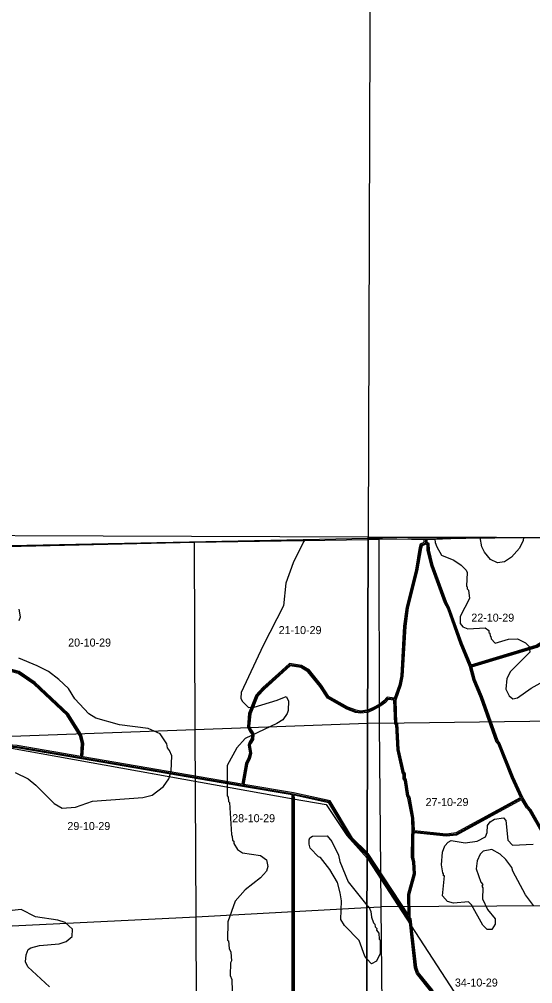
# Model space of a CAD drawing. Extents: x 457167 to 656239, y 1787309 to 1969297.
# Drawn here: x 527283 to 541715, y 1911287 to 1938392 of the extents above; entities that cross this region are included whole.
import ezdxf

# ---------------------------------------------------------------- set-up
doc = ezdxf.new("R2010")
doc.units = 0
for name, color, linetype in [('Level 1', 7, 'Continuous'), ('Level 10', 7, 'Continuous'), ('Level 2', 7, 'Continuous'), ('Level 22', 7, 'Continuous'), ('Level 23', 7, 'Continuous'), ('Level 31', 7, 'Continuous'), ('Level 32', 7, 'Continuous'), ('Level 34', 7, 'Continuous'), ('Level 55', 7, 'Continuous'), ('Level 63', 7, 'Continuous'), ('Level 7', 7, 'Continuous')]:
    doc.layers.add(name, color=color, linetype=linetype)

msp = doc.modelspace()

# ---------------------------------------------------------------- linework, layer by layer
at = {"layer": 'Level 1'}
for p, q in [((532207.788, 1923696.97), (537088.395, 1923773.153)), ((537088.395, 1923773.153), (537386.225, 1923777.802)), ((537386.225, 1923777.802), (541464.725, 1923829.241)), ((537386.225, 1923777.802), (537399.722, 1918609.551)), ((540899.182, 1923825.716), (541279.888, 1923829.737)), ((541279.889, 1923829.737), (541279.89, 1923829.737)), ((541279.89, 1923829.737), (541279.891, 1923829.737)), ((541279.891, 1923829.737), (541279.892, 1923829.737)), ((541279.892, 1923829.737), (541279.894, 1923829.737)), ((541279.894, 1923829.737), (541279.896, 1923829.737)), ((541279.896, 1923829.737), (541279.9, 1923829.737)), ((541279.9, 1923829.737), (541279.904, 1923829.737)), ((541279.904, 1923829.737), (541279.909, 1923829.737)), ((541279.909, 1923829.737), (542660.739, 1923844.323)), ((541464.726, 1923829.241), (541464.727, 1923829.241)), ((541464.726, 1923829.241), (541464.726, 1923829.241)), ((541464.727, 1923829.241), (541464.728, 1923829.241)), ((541464.728, 1923829.241), (541464.73, 1923829.241)), ((541464.73, 1923829.241), (541464.731, 1923829.241)), ((541464.731, 1923829.241), (541464.733, 1923829.241)), ((541464.733, 1923829.241), (541464.736, 1923829.241)), ((541464.736, 1923829.241), (541464.739, 1923829.241)), ((541464.739, 1923829.241), (541464.742, 1923829.241)), ((541464.742, 1923829.241), (541464.746, 1923829.241)), ((541464.746, 1923829.241), (541464.751, 1923829.241)), ((541464.751, 1923829.241), (541464.758, 1923829.241)), ((541464.758, 1923829.241), (541464.766, 1923829.241)), ((541464.766, 1923829.241), (541464.775, 1923829.241)), ((541464.775, 1923829.241), (541464.786, 1923829.241)), ((541464.786, 1923829.241), (541464.801, 1923829.241)), ((541464.801, 1923829.241), (541464.817, 1923829.241)), ((541464.817, 1923829.241), (541464.838, 1923829.241)), ((541464.838, 1923829.241), (541464.863, 1923829.241)), ((526935.17, 1923574.614), (532207.788, 1923696.97)), ((532229.194, 1918419.419), (532207.788, 1923696.97)), ((537071.765, 1918597.492), (532229.194, 1918419.419)), ((537399.722, 1918609.551), (537071.765, 1918597.492)), ((537399.722, 1918609.551), (542688.569, 1918676.008)), ((537399.722, 1918609.551), (537449.415, 1913450.626)), ((532229.194, 1918419.419), (527067.84, 1918235.886)), ((532250.887, 1913167.832), (532229.194, 1918419.419)), ((532250.887, 1913167.832), (537055.159, 1913429.178)), ((537055.159, 1913429.178), (537449.415, 1913450.626)), ((542719.505, 1913479.356), (537449.415, 1913450.626)), ((537449.415, 1913450.626), (537491.16, 1908193.626)), ((527082.764, 1912914.463), (532250.887, 1913167.832)), ((532281.084, 1907962.091), (532250.887, 1913167.832))]:
    msp.add_line(p, q, dxfattribs=at)
at = {"layer": 'Level 10'}
for points in [[(526576.251, 1923593.055), (537088.465, 1923809.196), (537088.51, 1923809.195)], [(537088.51, 1923809.195), (538706.499, 1923767.216), (540123.527, 1923831.236), (542887.584, 1923822.271), (543166.577, 1923824.675)]]:
    msp.add_lwpolyline(points, dxfattribs=at)
at = {"layer": 'Level 22'}
msp.add_line((538706.659, 1923677.254), (538706.944, 1923767.074), dxfattribs=at)
at = {"layer": 'Level 23'}
for p, q in [((538666.706, 1923692.391), (538666.947, 1923768.242)), ((538746.7, 1923689.914), (538746.951, 1923769.043))]:
    msp.add_line(p, q, dxfattribs=at)
at = {"layer": 'Level 31'}
for p, q in [((533564.628, 1916861.349), (529035.771, 1917636.671)), ((534984.082, 1916618.481), (533564.628, 1916861.349)), ((534984.26, 1916478.475), (534984.082, 1916618.481)), ((534986.798, 1910649.551), (534984.26, 1916478.475)), ((537059.931, 1914928.41), (537059.975, 1914928.342)), ((537059.975, 1914928.342), (538245.04, 1913122.737)), ((538270.068, 1913097.566), (538245.04, 1913122.737)), ((538287.69, 1912942.232), (538270.068, 1913097.566))]:
    msp.add_line(p, q, dxfattribs=at)
for points in [[(537851.535, 1919279.466), (537995.881, 1919700.836), (538046.517, 1919934.137), (538125.343, 1921334.296), (538193.43, 1921859.551), (538454.444, 1922900.938), (538564.518, 1923542.428), (538589.884, 1923625.623), (538706.659, 1923677.254)], [(539964.516, 1920212.431), (539699.585, 1920846.741), (539351.88, 1921831.144), (539260.604, 1922006.712), (538888.27, 1923033.017), (538780.977, 1923466.828), (538773.271, 1923641.768), (538706.659, 1923677.254)], [(529035.771, 1917636.671), (529066.382, 1918036.581), (528999.837, 1918277.181), (528641.777, 1918856.254), (527708.613, 1919728.246), (527267.972, 1920034.881), (526943.509, 1920121.473), (526847.193, 1920203.631), (526702.303, 1920661.61), (526702.662, 1920764.158), (526738.365, 1920978.223), (526712.279, 1921060.5), (526639.521, 1921154.576), (526598.766, 1921221.995), (526605.164, 1921415.434), (526552.704, 1921497.803), (526447.68, 1921542.173), (525921.774, 1921538.932)], [(539964.516, 1920212.431), (541825.21, 1920774.286), (542175.76, 1920998.301), (542551.24, 1921064.056), (542726.25, 1921038.791), (542825.899, 1920996.666), (543042.318, 1920795.996), (543300.811, 1920845.391)], [(537072.875, 1918943.056), (537072.848, 1918943.045), (536877.975, 1918920.401), (536740.444, 1918941.571), (536506.835, 1919027.785), (535966.66, 1919337.911), (535754.146, 1919655.341), (535416.143, 1920079.004), (535209.034, 1920200.048), (534887.299, 1920251.286), (534585.16, 1919979.906), (534151.372, 1919586.048), (533960.666, 1919381.581), (533760.062, 1918875.316), (533726.775, 1918515.051), (533781.998, 1918397.41), (533846.189, 1918300.466), (533833.955, 1918156.866), (533769.444, 1918060.348), (533742.835, 1917990.252), (533780.223, 1917764.302), (533741.613, 1917620.789), (533671.195, 1917468.653), (533564.628, 1916861.349)], [(541413.502, 1916507.061), (541148.339, 1917083.175), (540767.405, 1918034.574), (540717.376, 1918092.914), (540270.645, 1919336.169), (540071.99, 1919828.809), (539964.516, 1920212.431)], [(537851.535, 1919279.466), (537636.17, 1919307.065), (537551.665, 1919215.333), (537431.875, 1919120.442), (537230.367, 1919010.541), (537072.875, 1918943.056)], [(538359.919, 1915564.994), (538344.27, 1915940.328), (538237.412, 1916515.596), (538204.203, 1916565.886), (538138.556, 1917007.927), (538105.346, 1917057.854), (538105.745, 1917182.947), (538080.693, 1917199.756), (537932.505, 1917866.796), (537892.849, 1918584.037), (537867.798, 1918600.846), (537844.48, 1919259.487), (537851.535, 1919279.466)], [(529035.771, 1917636.671), (527219.39, 1917948.064), (526544.584, 1918000.608), (524894.144, 1918048.616), (524727.453, 1918090.664)], [(537059.931, 1914928.41), (536630.054, 1915361.81), (536000.334, 1916398.066), (534984.082, 1916618.481)], [(538359.919, 1915564.994), (539285.086, 1915470.782), (539568.359, 1915503.345), (541413.502, 1916507.061)], [(543546.401, 1912891.67), (541977.92, 1915580.194), (541646.004, 1916156.511), (541563.023, 1916248.406), (541413.502, 1916507.061)], [(538245.04, 1913122.737), (538230.028, 1913798.078), (538390.159, 1914381.223), (538374.35, 1914706.376), (538341.403, 1914839.939), (538342.995, 1915439.953), (538359.919, 1915564.994)], [(538909.852, 1909277.964), (538938.548, 1910611.731), (538972.581, 1910819.993), (538881.566, 1911086.835), (538474.405, 1911588.142), (538424.664, 1911738.486), (538287.69, 1912942.232)]]:
    msp.add_lwpolyline(points, dxfattribs=at)
at = {"layer": 'Level 32'}
for p, q in [((533559.566, 1916831.778), (529030.71, 1917607.1)), ((533540.244, 1916895.96), (529067.772, 1917661.628)), ((534954.115, 1916593.171), (533559.57, 1916831.777)), ((534989.795, 1916647.94), (533599.385, 1916885.838)), ((534954.26, 1916478.437), (534954.115, 1916593.171)), ((534956.786, 1910679.27), (534954.26, 1916478.461)), ((535014.26, 1916478.512), (535014.13, 1916581.265)), ((535016.789, 1910672.371), (535014.26, 1916478.488)), ((537036.507, 1914909.425), (537059.801, 1914873.933)), ((537059.801, 1914873.933), (538221.626, 1913103.736)), ((537083.357, 1914947.392), (537060.112, 1914970.828)), ((537083.357, 1914947.392), (538212.722, 1913226.652)), ((538241.436, 1913083.812), (538221.625, 1913103.736)), ((538257.881, 1912938.851), (538241.436, 1913083.812)), ((538298.702, 1913111.317), (538274.768, 1913135.388)), ((538317.5, 1912945.614), (538298.702, 1913111.317))]:
    msp.add_line(p, q, dxfattribs=at)
for points in [[(537831.084, 1919312.332), (537966.935, 1919708.906), (538016.697, 1919938.186), (538095.451, 1921337.072), (538163.903, 1921865.146), (538425.067, 1922907.131), (538535.27, 1923549.366), (538565.192, 1923647.509), (538666.706, 1923692.391)], [(537879.917, 1919269.742), (538024.829, 1919692.766), (538076.337, 1919930.087), (538155.235, 1921331.521), (538222.956, 1921853.958), (538483.82, 1922894.745), (538593.765, 1923535.489), (538614.575, 1923603.738), (538705.438, 1923643.911)], [(539936.125, 1920202.566), (539671.579, 1920835.956), (539324.292, 1921819.171), (539233.075, 1921994.625), (538859.527, 1923024.276), (538751.138, 1923462.524), (538744.053, 1923623.341), (538705.439, 1923643.911)], [(539981.765, 1920248.976), (539727.593, 1920857.527), (539379.468, 1921843.118), (539288.133, 1922018.8), (538917.013, 1923041.759), (538810.817, 1923471.132), (538802.489, 1923660.196), (538746.7, 1923689.915)], [(529067.771, 1917661.628), (529096.696, 1918039.521), (529027.609, 1918289.311), (528665.188, 1918875.439), (527727.52, 1919751.638), (527280.79, 1920062.511), (526957.81, 1920148.707), (526873.204, 1920220.877), (526732.32, 1920666.191), (526732.654, 1920761.621), (526769.145, 1920980.408), (526739.267, 1921074.642), (526664.305, 1921171.569), (526629.045, 1921229.898), (526635.455, 1921423.721), (526572.988, 1921521.801), (526453.669, 1921572.211), (525921.589, 1921568.932)], [(529008.374, 1917671.806), (529036.068, 1918033.639), (528972.065, 1918265.051), (528618.367, 1918837.07), (527689.706, 1919704.853), (527255.154, 1920007.251), (526929.209, 1920094.239), (526821.183, 1920186.386), (526672.285, 1920657.029), (526672.67, 1920766.696), (526707.585, 1920976.037), (526685.29, 1921046.357), (526614.738, 1921137.584), (526568.487, 1921214.091), (526574.872, 1921407.147), (526532.42, 1921473.805), (526441.691, 1921512.135), (525921.958, 1921508.932)], [(539981.765, 1920248.977), (541812.559, 1920801.803), (542164.667, 1921026.816), (542550.785, 1921094.434), (542734.366, 1921067.931), (542842.433, 1921022.248), (543051.59, 1920828.311), (543265.744, 1920869.232)], [(540001.337, 1920192.21), (541837.861, 1920746.767), (542186.852, 1920969.786), (542551.695, 1921033.68), (542718.134, 1921009.651), (542809.365, 1920971.085), (543033.045, 1920763.681), (543308.093, 1920816.237)], [(537072.98, 1918975.741), (537065.046, 1918972.341), (536878.535, 1918950.668), (536747.995, 1918970.763), (536519.586, 1919055.057), (535987.685, 1919360.433), (535778.379, 1919673.071), (535436.108, 1920102.084), (535219.31, 1920228.79), (534877.892, 1920283.162), (534565.053, 1920002.171), (534130.283, 1919607.422), (533934.863, 1919397.9), (533730.585, 1918882.365), (533696.15, 1918509.688), (533755.773, 1918382.676), (533815.41, 1918292.61), (533804.719, 1918167.112), (533742.606, 1918074.184), (533711.916, 1917993.336), (533749.563, 1917765.819), (533713.309, 1917631.061), (533642.323, 1917477.699), (533540.243, 1916895.96)], [(537072.778, 1918912.835), (536877.415, 1918890.133), (536732.892, 1918912.38), (536494.083, 1919000.512), (535945.636, 1919315.388), (535729.913, 1919637.61), (535396.178, 1920055.924), (535198.756, 1920171.306), (534896.705, 1920219.41), (534605.268, 1919957.641), (534172.461, 1919564.675), (533986.47, 1919365.261), (533789.54, 1918868.268), (533757.398, 1918520.414), (533808.224, 1918412.144), (533876.967, 1918308.324), (533863.192, 1918146.619), (533796.281, 1918046.512), (533773.754, 1917987.168), (533810.882, 1917762.786), (533769.916, 1917610.517), (533700.066, 1917459.607), (533599.386, 1916885.838)], [(541374.519, 1916520.005), (541120.77, 1917071.32), (540741.4, 1918018.813), (540691.01, 1918077.575), (540242.606, 1919325.482), (540043.548, 1919819.123), (539936.125, 1920202.566)], [(541440.174, 1916520.868), (541175.908, 1917095.029), (540793.41, 1918050.335), (540743.744, 1918108.253), (540298.684, 1919346.856), (540100.432, 1919838.495), (540001.337, 1920192.211)], [(537814.658, 1919253.946), (537647.732, 1919275.337), (537572.136, 1919193.277), (537448.493, 1919095.333), (537243.487, 1918983.523), (537080.649, 1918913.749), (537072.778, 1918912.835)], [(537831.083, 1919312.332), (537624.607, 1919338.793), (537531.193, 1919237.39), (537415.258, 1919145.551), (537217.247, 1919037.557), (537072.98, 1918975.741)], [(538329.835, 1915566.391), (538314.385, 1915936.946), (538209.026, 1916504.139), (538175.504, 1916554.902), (538109.865, 1916996.891), (538075.316, 1917048.831), (538075.693, 1917166.982), (538054.009, 1917181.531), (537902.687, 1917862.687), (537863.72, 1918567.454), (537838.358, 1918584.471), (537814.658, 1919253.946)], [(538388.811, 1915592.207), (538374.155, 1915943.71), (538265.797, 1916527.053), (538232.901, 1916576.87), (538167.246, 1917018.963), (538135.376, 1917066.877), (538135.797, 1917198.911), (538107.376, 1917217.981), (537962.325, 1917870.905), (537921.979, 1918600.621), (537897.237, 1918617.221), (537874.664, 1919254.863), (537879.917, 1919269.742)], [(529030.703, 1917607.101), (527215.683, 1917918.261), (526542.982, 1917970.641), (524889.989, 1918018.723), (524712.034, 1918063.612)], [(529008.374, 1917671.806), (527223.097, 1917977.867), (526546.185, 1918030.575), (524898.298, 1918078.508), (524742.874, 1918117.714)], [(537060.112, 1914970.828), (536653.85, 1915380.42), (536019.282, 1916424.655), (534989.795, 1916647.939)], [(537036.507, 1914909.425), (536606.257, 1915343.2), (535981.385, 1916371.478), (535014.13, 1916581.266)], [(538385.756, 1915532.206), (539285.281, 1915440.606), (539577.575, 1915474.206), (541402.16, 1916466.736)], [(538388.811, 1915592.206), (539284.89, 1915500.958), (539559.142, 1915532.483), (541374.519, 1916520.006)], [(543520.965, 1912875.735), (541951.965, 1915565.148), (541621.599, 1916138.773), (541538.635, 1916230.651), (541402.16, 1916466.736)], [(543554.613, 1912937.13), (542003.876, 1915595.24), (541670.408, 1916174.248), (541587.411, 1916266.162), (541440.174, 1916520.868)], [(538212.722, 1913226.652), (538199.937, 1913801.795), (538359.961, 1914384.55), (538344.525, 1914702.014), (538311.393, 1914836.332), (538312.999, 1915442.013), (538329.835, 1915566.391)], [(538274.768, 1913135.388), (538260.119, 1913794.362), (538420.357, 1914377.897), (538404.173, 1914710.736), (538371.414, 1914843.545), (538372.99, 1915437.892), (538385.755, 1915532.206)], [(538880.801, 1909322.385), (538908.6, 1910614.486), (538941.761, 1910817.417), (538854.901, 1911072.079), (538447.651, 1911573.497), (538395.206, 1911732.011), (538257.882, 1912938.841)], [(538940.499, 1909307.654), (538968.495, 1910608.975), (539003.4, 1910822.568), (538908.232, 1911101.591), (538501.16, 1911602.786), (538454.121, 1911744.963), (538317.498, 1912945.625)]]:
    msp.add_lwpolyline(points, dxfattribs=at)
at = {"layer": 'Level 55'}
for p, q in [((537059.6, 1914811.626), (537106.107, 1914759.527)), ((538287.69, 1912942.232), (537106.107, 1914759.527)), ((540760.35, 1909140.507), (538287.69, 1912942.232))]:
    msp.add_line(p, q, dxfattribs=at)
for points in [[(524583.201, 1918098.086), (524699.025, 1917960.578), (525955.115, 1917920.131), (527064.494, 1917910.421), (534984.26, 1916478.475)], [(534984.26, 1916478.475), (535911.106, 1916323.445), (536490.815, 1915448.808), (537059.6, 1914811.626)]]:
    msp.add_lwpolyline(points, dxfattribs=at)
at = {"layer": 'Level 63'}
for points in [[(537088.613, 1923840.983), (576805.547, 1923734.416), (576903.181, 1969190.287), (537235.231, 1969297.112), (537088.613, 1923840.983)], [(497176.54, 1878534.741), (536942.563, 1878385.707), (537088.612, 1923840.983), (497371.386, 1923990.389), (497176.54, 1878534.741)], [(536942.563, 1878385.707), (576708.29, 1878279.4), (576805.546, 1923734.416), (537088.612, 1923840.983), (536942.563, 1878385.707)]]:
    msp.add_lwpolyline(points, dxfattribs=at)
at = {"layer": 'Level 7'}
msp.add_line((537050.655, 1911983.576), (537050.515, 1911983.757), dxfattribs=at)
for points in [[(535322.481, 1923772.886), (535270.889, 1923701.94), (534977.252, 1923119.342), (534775.357, 1922544.756), (534706.606, 1921903.09), (534136.183, 1920796.186), (533523.382, 1919472.667), (533514.525, 1919314.274), (533547.606, 1919230.812), (533722.083, 1919046.861), (533888.836, 1919054.672), (534531.356, 1919252.686), (534781.81, 1919360.241), (534848.103, 1919234.959), (534838.887, 1918968.233), (534813.618, 1918884.971), (534687.988, 1918701.965), (534520.936, 1918602.45), (533635.945, 1918180.139), (533401.675, 1917914.129), (533124.978, 1917423.164), (533130.572, 1916564.514), (533155.483, 1916531.074), (533163.395, 1916406.001), (533188.336, 1916380.921), (533243.782, 1915480.4), (533268.633, 1915421.979), (533276.645, 1915321.906), (533309.886, 1915288.466), (533309.697, 1915230.115), (533417.512, 1915054.692), (533558.936, 1914962.531), (534067.218, 1914894.206), (534233.553, 1914768.636), (534266.277, 1914576.801), (534232.549, 1914451.858), (534065.198, 1914260.641), (533630.635, 1913928.598), (533354.485, 1913604.357), (533144.22, 1913021.471), (533134.248, 1912512.979), (533159.19, 1912487.908), (533183.513, 1912279.404), (533224.865, 1912170.901), (533249.1, 1911929.076), (533223.89, 1911870.785), (533214.446, 1911520.696), (533255.729, 1911403.854), (533263.025, 1911078.706)], [(538962.659, 1923778.789), (538972.225, 1923690.047), (539021.848, 1923564.865), (539154.475, 1923330.991), (539495.814, 1923188.192), (539703.79, 1923054.132), (539845.055, 1922911.991), (539869.837, 1922845.199), (539851.953, 1922461.79), (539876.894, 1922445.02), (539876.705, 1922386.668), (539909.916, 1922344.888), (539942.51, 1922111.373), (539674.113, 1921603.697), (539673.496, 1921411.963), (539748.229, 1921320.031), (539889.783, 1921261.222), (540381.693, 1921284.659), (540481.495, 1921209.308), (540481.336, 1921159.287), (540506.277, 1921142.517), (540514.349, 1921059.126), (540539.3, 1921042.386), (540547.44, 1920975.664), (540663.755, 1920858.592), (541030.94, 1920974.13), (541289.376, 1920981.613), (541514.092, 1920864.184), (541613.806, 1920763.822), (541638.319, 1920605.369), (541094.696, 1920065.229), (540985.707, 1919865.523), (540959.711, 1919565.476), (541050.796, 1919373.442), (541158.9, 1919289.761), (541284.082, 1919322.674), (541668.435, 1919596.566), (541927.289, 1919729.102)], [(541456.414, 1923826.913), (541448.275, 1923740.461), (541339.217, 1923524.074), (541121.686, 1923274.666), (540921.194, 1923141.94), (540729.36, 1923117.546), (540529.585, 1923209.876), (540363.538, 1923418.839), (540288.975, 1923569.121), (540240.795, 1923830.856)], [(527277.561, 1921493.425), (527319.57, 1921601.667), (527278.575, 1921810.212)], [(527163.85, 1917225.573), (527530.061, 1917040.993), (527746.219, 1916865.212), (528261.437, 1916355.066), (528486.095, 1916220.956), (528861.321, 1916253.091), (529345.388, 1916418.252), (530754.555, 1916522.112), (531021.549, 1916587.957), (531339.081, 1916828.697), (531489.85, 1917044.954), (531548.889, 1917261.5), (531566.961, 1917694.931), (531509.068, 1917845.173), (531450.975, 1917920.405), (531426.293, 1918028.836), (531243.805, 1918312.861), (530902.475, 1918455.69), (530102.548, 1918566.612), (529436.231, 1918752.178), (529236.515, 1918869.508), (528846.08, 1919295.933), (528663.591, 1919579.957), (528397.652, 1919839.23), (528106.592, 1920056.931), (527782.003, 1920224.701), (527265.829, 1920434.74)], [(541740.503, 1913485.722), (541516.404, 1913786.546), (541160.066, 1914446.297), (541127.044, 1914554.77), (540961.037, 1914780.373), (540803.142, 1914930.954), (540570.115, 1915056.754), (540319.891, 1915007.52), (540236.23, 1914924.416), (540152.282, 1914741.311), (540126.555, 1914516.296), (540258.734, 1914140.728), (540308.555, 1914073.877), (540283.375, 1914023.956), (540308.257, 1913982.176), (540298.941, 1913673.768), (540448.02, 1913373.163), (540655.578, 1913105.749), (540655.08, 1912955.696), (540562.89, 1912805.931), (540437.878, 1912814.66), (540313.234, 1912931.761), (539989.938, 1913508.02), (539906.835, 1913591.641), (539489.887, 1913551.305), (539323.334, 1913593.544), (539182.098, 1913752.386), (539233.95, 1914319.1), (539208.94, 1914319.159), (539209.099, 1914377.521), (539184.188, 1914402.621), (539151.564, 1914627.806), (539177.719, 1914986.165), (539244.967, 1915161.04), (539337.017, 1915269.113), (539420.518, 1915310.536), (539812.127, 1915242.569), (540154.043, 1915291.505), (540387.885, 1915415.801), (540429.925, 1915532.384), (540447.252, 1915732.389), (540514.272, 1915832.191), (540639.543, 1915906.826), (540889.767, 1915947.69), (540956.23, 1915872.468), (541012.82, 1915322.076), (541145.745, 1915179.935), (541729.385, 1915211.413)], [(537050.515, 1911983.757), (536992.532, 1912058.767), (536835.582, 1912501.116), (536428.437, 1912919.241), (536320.622, 1913094.663), (536338.954, 1913619.786), (536306.33, 1913836.631), (536223.883, 1914128.666), (536016.653, 1914496.152), (535750.962, 1914830.457), (535692.711, 1914855.666), (535460.042, 1915098.14), (535427.06, 1915206.641), (535427.448, 1915331.685), (535452.647, 1915389.946), (535527.808, 1915431.398), (535936.356, 1915446.764), (536069.211, 1915287.941), (536259.711, 1914895.515), (536292.495, 1914720.351), (536524.089, 1914152.731), (537055.363, 1913492.581)], [(537055.363, 1913492.581), (537055.49, 1913492.422), (537105.372, 1913450.611), (537163.305, 1913317.029), (537179.458, 1913158.576), (537237.321, 1912999.993), (537278.873, 1912958.182), (537286.945, 1912883.151), (537328.496, 1912841.301), (537328.337, 1912791.289), (537386.43, 1912707.758), (537402.582, 1912540.964), (537427.453, 1912507.554), (537426.28, 1912132.425), (537325.56, 1911924.338), (537183.58, 1911841.435), (537050.655, 1911983.576), (537050.655, 1911983.576)], [(528136.541, 1911195.214), (527521.45, 1911764.049), (527455.186, 1911897.661), (527480.844, 1912097.636), (527531.352, 1912247.531), (527606.543, 1912297.313), (527848.496, 1912363.217), (528407.196, 1912411.446), (528599.12, 1912469.21), (528766.31, 1912610.375), (528775.297, 1912818.75), (528575.85, 1913011.132), (528367.635, 1913070.141), (527734.37, 1913163.905), (527334.879, 1913373.585), (526309.15, 1913260.179)]]:
    msp.add_lwpolyline(points, dxfattribs=at)

# ---------------------------------------------------------------- texts
at = {"layer": 'Level 2'}
for s, p in [('22-10-29', (539988.814, 1921462.34)), ('21-10-29', (534573.45, 1921112.76)), ('20-10-29', (528657.02, 1920762.555)), ('27-10-29', (538704.104, 1916280.038)), ('28-10-29', (533268.545, 1915825.576)), ('29-10-29', (528635.784, 1915605.332)), ('34-10-29', (539528.195, 1911206.437))]:
    msp.add_text(s, height=225, dxfattribs=at).set_placement(p)
at = {"layer": 'Level 34'}
for s, rotation, p in [('COUNTY', 89.8171, (538699.065, 1923643.26)), ('13', 89.8171, (538739.329, 1923726.666)), ('HWY', 89.8171, (538740.028, 1923651.917)), ('OLD BRICK ROAD', 289.9394139, (539018.38, 1922637.736)), ('DIRT ROAD', 16.8013722, (540822.042, 1920458.314)), ('OLD BRICK ROAD', 289.7637389, (540406.613, 1918910.655))]:
    msp.add_text(s, height=25, rotation=rotation, dxfattribs=at).set_placement(p)

doc.saveas('drawing.dxf')
